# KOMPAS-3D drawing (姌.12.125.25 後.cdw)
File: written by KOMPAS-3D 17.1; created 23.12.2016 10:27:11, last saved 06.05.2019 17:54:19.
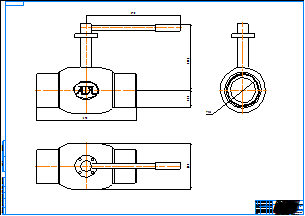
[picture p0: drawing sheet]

Sheet 1: A0, landscape

Title block, sheet 1: name: КШ.12.125.25 сс; material: Внимание! Данный продукт является объектом авторского права ООО «Торговый Дом АДЛ». / Запрещается изменение, копирование, распространение / (в том числе путем копирования на другие сайты и ресурсы в Интернете) / или любое иное использование информации и объектов без предварительного / согласия правообладателя (ООО «Торговый Дом АДЛ»).; sheets: 1; organisation: ООО "Торговый дом АДЛ"; sheet format: A0; stored path: C:\Users\tra\Desktop\2д чертежи\Шаровые краны БИВАЛ\КШ_Бивал_серия_11_12\KOMPAS_2D\КШ.12.125.25 сс.cdw

Views: Вид 1, Проекционный вид 2, Проекционный вид 3
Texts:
  Klimkovich
  ADL
Dimensions and other numbers on the sheet: 390; 370; 258,4; 66,5; 123; 180; 1:1; 1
